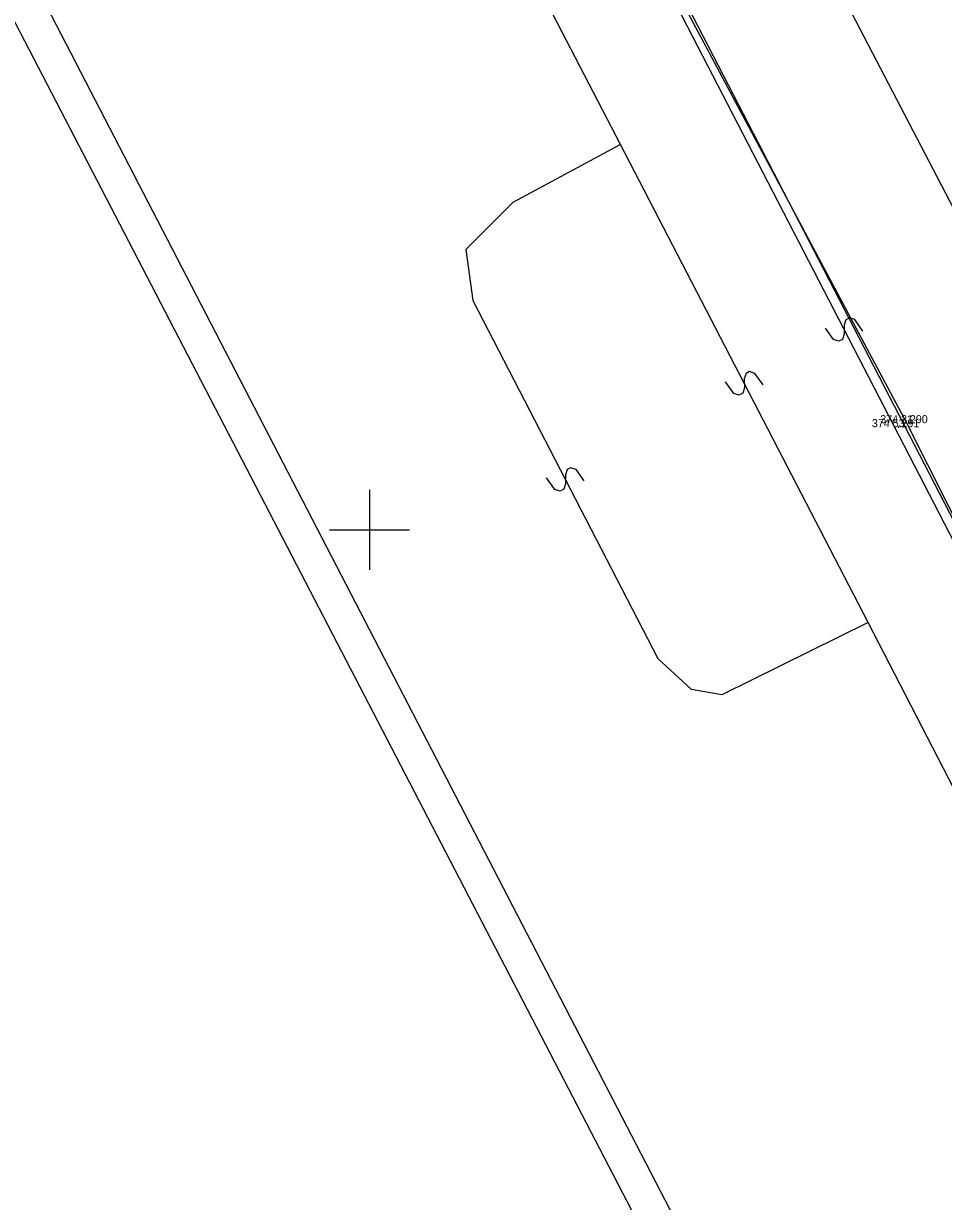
# Model space of a CAD drawing. Extents: x -601196 to -600262, y -1082523 to -1081922.
# Drawn here: x -600508.65 to -600485.65, y -1082316.78 to -1082287.34 of the extents above; entities that cross this region are included whole.
import ezdxf

# ---------------------------------------------------------------- set-up
doc = ezdxf.new("R2010")
doc.units = 0
for name, color, linetype in [('Vrstva 1', 7, 'Continuous'), ('Vrstva 10', 7, 'Continuous'), ('Vrstva 2', 7, 'Continuous'), ('Vrstva 20', 7, 'Continuous'), ('Vrstva 3', 7, 'Continuous'), ('Vrstva 47', 7, 'Continuous'), ('Vrstva 61', 7, 'Continuous')]:
    doc.layers.add(name, color=color, linetype=linetype)

msp = doc.modelspace()

# ---------------------------------------------------------------- linework, layer by layer
at = {"layer": 'Vrstva 1'}
for p, q in [((-600486.77, -1082297.43), (-600486.77, -1082297.43)), ((-600486.56, -1082297.33), (-600486.56, -1082297.33))]:
    msp.add_line(p, q, dxfattribs=at)
at = {"layer": 'Vrstva 10'}
for p, q in [((-600486.56, -1082297.33), (-600492.46, -1082286.27)), ((-600483.44, -1082303.54), (-600486.56, -1082297.33))]:
    msp.add_line(p, q, dxfattribs=at)
at = {"layer": 'Vrstva 20'}
for p, q in [((-600486.78, -1082297.43), (-600486.76, -1082297.43)), ((-600486.77, -1082297.415), (-600486.77, -1082297.43)), ((-600486.77, -1082297.445), (-600486.77, -1082297.43))]:
    msp.add_line(p, q, dxfattribs=at)
at = {"layer": 'Vrstva 47'}
for p, q in [((-600496.18, -1082271.26), (-600476.01, -1082310)), ((-600493.72, -1082290.36), (-600500.7, -1082276.91)), ((-600500.34, -1082301.83), (-600510.99, -1082281.27)), ((-600472.11, -1082358.06), (-600511.64, -1082281.96)), ((-600483.07, -1082304.26), (-600493.08, -1082284.9)), ((-600483.54, -1082303.87), (-600492.72, -1082286.11)), ((-600493.72, -1082290.36), (-600496.41, -1082291.81)), ((-600487.53, -1082302.31), (-600493.72, -1082290.36)), ((-600496.41, -1082291.81), (-600497.59, -1082292.99)), ((-600497.59, -1082292.99), (-600497.41, -1082294.26)), ((-600497.41, -1082294.26), (-600492.79, -1082303.21)), ((-600488.088, -1082294.743), (-600488.131, -1082294.878)), ((-600487.999, -1082294.697), (-600488.088, -1082294.743)), ((-600487.865, -1082294.74), (-600487.999, -1082294.697)), ((-600487.659, -1082295.028), (-600487.865, -1082294.74)), ((-600488.395, -1082295.239), (-600488.6, -1082294.951)), ((-600488.128, -1082295.101), (-600488.171, -1082295.236)), ((-600488.131, -1082294.878), (-600488.128, -1082295.101)), ((-600488.26, -1082295.282), (-600488.395, -1082295.239)), ((-600488.171, -1082295.236), (-600488.26, -1082295.282)), ((-600490.889, -1082296.584), (-600491.095, -1082296.297)), ((-600490.583, -1082296.088), (-600490.626, -1082296.223)), ((-600490.626, -1082296.223), (-600490.623, -1082296.446)), ((-600490.495, -1082296.042), (-600490.583, -1082296.088)), ((-600490.36, -1082296.085), (-600490.495, -1082296.042)), ((-600490.154, -1082296.373), (-600490.36, -1082296.085)), ((-600490.755, -1082296.627), (-600490.889, -1082296.584)), ((-600490.666, -1082296.581), (-600490.755, -1082296.627)), ((-600490.623, -1082296.446), (-600490.666, -1082296.581)), ((-600495.058, -1082298.488), (-600495.101, -1082298.623)), ((-600495.101, -1082298.623), (-600495.098, -1082298.846)), ((-600494.969, -1082298.442), (-600495.058, -1082298.488)), ((-600494.834, -1082298.485), (-600494.969, -1082298.442)), ((-600494.629, -1082298.773), (-600494.834, -1082298.485)), ((-600495.365, -1082298.984), (-600495.57, -1082298.696)), ((-600495.098, -1082298.846), (-600495.141, -1082298.981)), ((-600495.23, -1082299.027), (-600495.365, -1082298.984)), ((-600495.141, -1082298.981), (-600495.23, -1082299.027)), ((-600490.04, -1082321.7), (-600500.34, -1082301.83)), ((-600487.53, -1082302.31), (-600491.19, -1082304.12)), ((-600480.66, -1082315.64), (-600487.53, -1082302.31)), ((-600491.95, -1082303.99), (-600492.79, -1082303.21)), ((-600491.19, -1082304.12), (-600491.95, -1082303.99))]:
    msp.add_line(p, q, dxfattribs=at)
at = {"layer": 'Vrstva 61'}
for p, q in [((-600500, -1082299), (-600500, -1082301)), ((-600500, -1082299), (-600500, -1082301)), ((-600501, -1082300), (-600499, -1082300)), ((-600501, -1082300), (-600499, -1082300))]:
    msp.add_line(p, q, dxfattribs=at)

# ---------------------------------------------------------------- texts
at = {"layer": 'Vrstva 2'}
for s, p in [(' 290', (-600486.56, -1082297.33)), (' 291', (-600486.77, -1082297.43))]:
    msp.add_text(s, height=0.2, dxfattribs=at).set_placement(p)
at = {"layer": 'Vrstva 3'}
for s, p in [('374 31 ', (-600487.226, -1082297.33)), ('374 53 ', (-600487.436, -1082297.43))]:
    msp.add_text(s, height=0.2, dxfattribs=at).set_placement(p)

doc.saveas('drawing.dxf')
